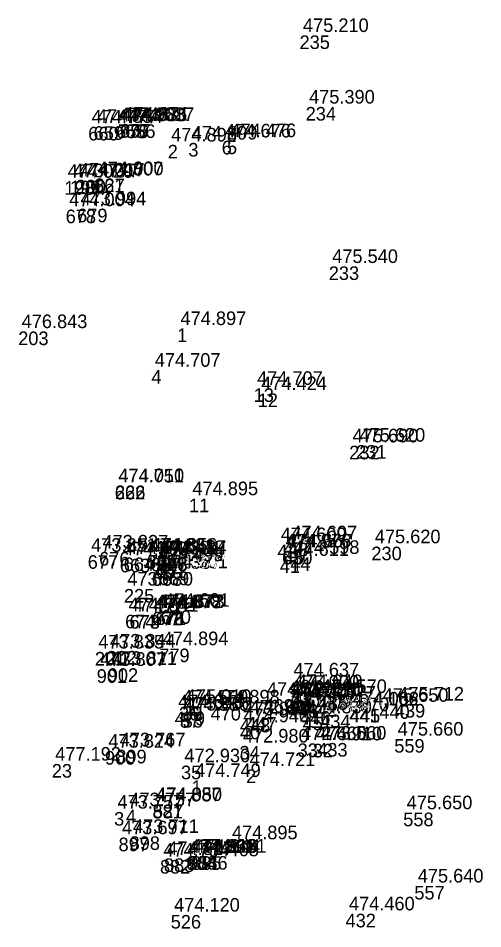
# Model space of a CAD drawing. Extents: x -874038 to -859694, y -1059487 to -1049069.
# Drawn here: x -866291.5 to -866250.5, y -1053623.2 to -1053542.8 of the extents above; entities that cross this region are included whole.
import ezdxf

# ---------------------------------------------------------------- set-up
doc = ezdxf.new("R2010")
doc.units = 0
doc.layers.add('Vrstva 60', color=7, linetype='Continuous')
doc.layers.add('Vrstva 61', color=7, linetype='Continuous')

msp = doc.modelspace()

# ---------------------------------------------------------------- linework, layer by layer
at = {"layer": 'Vrstva 60'}
for p, q in [((-866266.66, -1053544.29), (-866266.66, -1053544.29)), ((-866266.12, -1053550.61), (-866266.12, -1053550.61)), ((-866285.309, -1053552.368), (-866285.309, -1053552.368)), ((-866284.837, -1053552.312), (-866284.837, -1053552.312)), ((-866282.84, -1053552.167), (-866282.84, -1053552.167)), ((-866282.67, -1053552.158), (-866282.67, -1053552.158)), ((-866282.504, -1053552.123), (-866282.504, -1053552.123)), ((-866282.052, -1053552.148), (-866282.052, -1053552.148)), ((-866273.528, -1053553.602), (-866273.528, -1053553.602)), ((-866273.063, -1053553.574), (-866273.063, -1053553.574)), ((-866278.293, -1053553.959), (-866278.293, -1053553.959)), ((-866276.474, -1053553.789), (-866276.474, -1053553.789)), ((-866287.42, -1053557.163), (-866287.42, -1053557.163)), ((-866286.917, -1053557.123), (-866286.917, -1053557.123)), ((-866286.424, -1053557.048), (-866286.424, -1053557.048)), ((-866284.792, -1053556.958), (-866284.792, -1053556.958)), ((-866284.76, -1053556.93), (-866284.76, -1053556.93)), ((-866287.297, -1053559.672), (-866287.297, -1053559.672)), ((-866286.287, -1053559.592), (-866286.287, -1053559.592)), ((-866264.08, -1053564.69), (-866264.08, -1053564.69)), ((-866291.485, -1053570.442), (-866291.485, -1053570.442)), ((-866277.464, -1053570.168), (-866277.464, -1053570.168)), ((-866279.734, -1053573.851), (-866279.734, -1053573.851)), ((-866270.709, -1053575.454), (-866270.709, -1053575.454)), ((-866270.35, -1053575.915), (-866270.35, -1053575.915)), ((-866262.28, -1053580.53), (-866262.28, -1053580.53)), ((-866261.67, -1053580.47), (-866261.67, -1053580.47)), ((-866282.964, -1053584.073), (-866282.964, -1053584.073)), ((-866282.94, -1053584.04), (-866282.94, -1053584.04)), ((-866276.418, -1053585.197), (-866276.418, -1053585.197)), ((-866268.617, -1053589.257), (-866268.617, -1053589.257)), ((-866268.204, -1053589.812), (-866268.204, -1053589.812)), ((-866268.058, -1053589.809), (-866268.058, -1053589.809)), ((-866267.68, -1053589.093), (-866267.68, -1053589.093)), ((-866260.32, -1053589.44), (-866260.32, -1053589.44)), ((-866285.354, -1053590.193), (-866285.354, -1053590.193)), ((-866284.349, -1053589.908), (-866284.349, -1053589.908)), ((-866282.521, -1053590.507), (-866282.521, -1053590.507)), ((-866282.18, -1053590.397), (-866282.18, -1053590.397)), ((-866280.194, -1053590.203), (-866280.194, -1053590.203)), ((-866280.02, -1053590.185), (-866280.02, -1053590.185)), ((-866279.797, -1053590.432), (-866279.797, -1053590.432)), ((-866279.219, -1053590.378), (-866279.219, -1053590.378)), ((-866279.208, -1053590.399), (-866279.208, -1053590.399)), ((-866268.403, -1053590.552), (-866268.403, -1053590.552)), ((-866267.477, -1053590.382), (-866267.477, -1053590.382)), ((-866279.483, -1053591.029), (-866279.483, -1053591.029)), ((-866279.339, -1053590.998), (-866279.339, -1053590.998)), ((-866279.699, -1053591.698), (-866279.699, -1053591.698)), ((-866279.084, -1053591.643), (-866279.084, -1053591.643)), ((-866282.16, -1053593.18), (-866282.16, -1053593.18)), ((-866282.052, -1053595.45), (-866282.052, -1053595.45)), ((-866279.67, -1053595.187), (-866279.67, -1053595.187)), ((-866279.5, -1053595.169), (-866279.5, -1053595.169)), ((-866279.361, -1053595.157), (-866279.361, -1053595.157)), ((-866278.924, -1053595.053), (-866278.924, -1053595.053)), ((-866281.664, -1053595.483), (-866281.664, -1053595.483)), ((-866283.691, -1053598.653), (-866283.691, -1053598.653)), ((-866279.039, -1053598.442), (-866279.039, -1053598.442)), ((-866284.721, -1053598.737), (-866284.721, -1053598.737)), ((-866284.559, -1053600.268), (-866284.559, -1053600.268)), ((-866283.584, -1053600.183), (-866283.584, -1053600.183)), ((-866267.5, -1053601.203), (-866267.5, -1053601.203)), ((-866267.51, -1053602.29), (-866267.51, -1053602.29)), ((-866267.21, -1053602.23), (-866267.21, -1053602.23)), ((-866265.06, -1053602.66), (-866265.06, -1053602.66)), ((-866269.841, -1053602.908), (-866269.841, -1053602.908)), ((-866267.787, -1053603.047), (-866267.787, -1053603.047)), ((-866267.685, -1053603.337), (-866267.685, -1053603.337)), ((-866267.4, -1053602.93), (-866267.4, -1053602.93)), ((-866267.13, -1053602.95), (-866267.13, -1053602.95)), ((-866266.018, -1053603.251), (-866266.018, -1053603.251)), ((-866259.62, -1053603.44), (-866259.62, -1053603.44)), ((-866258.251, -1053603.333), (-866258.251, -1053603.333)), ((-866277.677, -1053604), (-866277.677, -1053604)), ((-866277.3, -1053603.59), (-866277.3, -1053603.59)), ((-866277.23, -1053604.23), (-866277.23, -1053604.23)), ((-866277.01, -1053603.54), (-866277.01, -1053603.54)), ((-866276.97, -1053604.21), (-866276.97, -1053604.21)), ((-866274.513, -1053603.588), (-866274.513, -1053603.588)), ((-866266.619, -1053603.96), (-866266.619, -1053603.96)), ((-866264.84, -1053604.27), (-866264.84, -1053604.27)), ((-866262.268, -1053603.752), (-866262.268, -1053603.752)), ((-866262.218, -1053603.768), (-866262.218, -1053603.768)), ((-866271.915, -1053604.639), (-866271.915, -1053604.639)), ((-866271.355, -1053604.476), (-866271.355, -1053604.476)), ((-866266.38, -1053604.46), (-866266.38, -1053604.46)), ((-866271.92, -1053605.25), (-866271.92, -1053605.25)), ((-866258.3, -1053606.43), (-866258.3, -1053606.43)), ((-866283.827, -1053607.492), (-866283.827, -1053607.492)), ((-866282.832, -1053607.378), (-866282.832, -1053607.378)), ((-866271.96, -1053607.04), (-866271.96, -1053607.04)), ((-866266.83, -1053606.82), (-866266.83, -1053606.82)), ((-866265.49, -1053606.85), (-866265.49, -1053606.85)), ((-866265.1, -1053606.78), (-866265.1, -1053606.78)), ((-866288.522, -1053608.638), (-866288.522, -1053608.638)), ((-866277.12, -1053608.78), (-866277.12, -1053608.78)), ((-866271.368, -1053609.114), (-866271.368, -1053609.114)), ((-866276.185, -1053610.084), (-866276.185, -1053610.084)), ((-866279.642, -1053612.238), (-866279.642, -1053612.238)), ((-866279.6, -1053612.2), (-866279.6, -1053612.2)), ((-866283.026, -1053612.874), (-866283.026, -1053612.874)), ((-866281.981, -1053612.667), (-866281.981, -1053612.667)), ((-866257.51, -1053612.93), (-866257.51, -1053612.93)), ((-866282.632, -1053615.138), (-866282.632, -1053615.138)), ((-866281.654, -1053615.023), (-866281.654, -1053615.023)), ((-866272.931, -1053615.579), (-866272.931, -1053615.579)), ((-866278.977, -1053617.112), (-866278.977, -1053617.112)), ((-866278.629, -1053616.968), (-866278.629, -1053616.968)), ((-866276.634, -1053616.793), (-866276.634, -1053616.793)), ((-866276.461, -1053616.766), (-866276.461, -1053616.766)), ((-866276.227, -1053616.782), (-866276.227, -1053616.782)), ((-866275.684, -1053616.763), (-866275.684, -1053616.763)), ((-866256.53, -1053619.4), (-866256.53, -1053619.4)), ((-866278.03, -1053621.97), (-866278.03, -1053621.97)), ((-866262.6, -1053621.86), (-866262.6, -1053621.86))]:
    msp.add_line(p, q, dxfattribs=at)

# ---------------------------------------------------------------- texts
for s, p in [('235', (-866266.66, -1053545.49)), ('234', (-866266.12, -1053551.81)), ('660', (-866285.309, -1053553.568)), ('659', (-866284.837, -1053553.512)), ('658', (-866282.84, -1053553.367)), ('776', (-866282.67, -1053553.358)), ('657', (-866282.504, -1053553.323)), ('656', (-866282.052, -1053553.348)), ('6', (-866273.528, -1053554.802)), ('5', (-866273.063, -1053554.774)), ('2', (-866278.293, -1053555.159)), ('3', (-866276.474, -1053554.989)), ('198', (-866287.42, -1053558.363)), ('199', (-866286.917, -1053558.323)), ('200', (-866286.424, -1053558.248)), ('661', (-866284.792, -1053558.158)), ('227', (-866284.76, -1053558.13)), ('678', (-866287.297, -1053560.872)), ('679', (-866286.287, -1053560.792)), ('233', (-866264.08, -1053565.89)), ('203', (-866291.485, -1053571.642)), ('1', (-866277.464, -1053571.368)), ('4', (-866279.734, -1053575.051)), ('13', (-866270.709, -1053576.654)), ('12', (-866270.35, -1053577.115)), ('232', (-866262.28, -1053581.73)), ('231', (-866261.67, -1053581.67)), ('662', (-866282.964, -1053585.273)), ('226', (-866282.94, -1053585.24)), ('11', (-866276.418, -1053586.397)), ('42', (-866268.617, -1053590.457)), ('630', (-866268.204, -1053591.012)), ('45', (-866268.058, -1053591.009)), ('43', (-866267.68, -1053590.293)), ('230', (-866260.32, -1053590.64)), ('677', (-866285.354, -1053591.393)), ('676', (-866284.349, -1053591.108)), ('663', (-866282.521, -1053591.707)), ('664', (-866282.18, -1053591.597)), ('665', (-866280.194, -1053591.403)), ('777', (-866280.02, -1053591.385)), ('667', (-866279.797, -1053591.632)), ('666', (-866279.219, -1053591.578)), ('928', (-866279.208, -1053591.599)), ('41', (-866268.403, -1053591.752)), ('44', (-866267.477, -1053591.582)), ('40', (-866279.483, -1053592.229)), ('651', (-866279.339, -1053592.198)), ('668', (-866279.699, -1053592.898)), ('669', (-866279.084, -1053592.843)), ('225', (-866282.16, -1053594.38)), ('674', (-866282.052, -1053596.65)), ('672', (-866279.67, -1053596.387)), ('778', (-866279.5, -1053596.369)), ('671', (-866279.361, -1053596.357)), ('670', (-866278.924, -1053596.253)), ('673', (-866281.664, -1053596.683)), ('202', (-866283.691, -1053599.853)), ('779', (-866279.039, -1053599.642)), ('201', (-866284.721, -1053599.937)), ('901', (-866284.559, -1053601.468)), ('902', (-866283.584, -1053601.383)), ('481', (-866267.5, -1053602.403)), ('43', (-866267.51, -1053603.49)), ('42', (-866267.21, -1053603.43)), ('435', (-866265.06, -1053603.86)), ('469', (-866269.841, -1053604.108)), ('444', (-866267.787, -1053604.247)), ('443', (-866267.685, -1053604.537)), ('44', (-866267.4, -1053604.13)), ('41', (-866267.13, -1053604.15)), ('442', (-866266.018, -1053604.451)), ('440', (-866259.62, -1053604.64)), ('439', (-866258.251, -1053604.533)), ('479', (-866277.677, -1053605.2)), ('36', (-866277.3, -1053604.79)), ('37', (-866277.23, -1053605.43)), ('39', (-866277.01, -1053604.74)), ('38', (-866276.97, -1053605.41)), ('470', (-866274.513, -1053604.788)), ('446', (-866266.619, -1053605.16)), ('434', (-866264.84, -1053605.47)), ('441', (-866262.268, -1053604.952)), ('445', (-866262.218, -1053604.968)), ('448', (-866271.915, -1053605.839)), ('447', (-866271.355, -1053605.676)), ('45', (-866266.38, -1053605.66)), ('40', (-866271.92, -1053606.45)), ('559', (-866258.3, -1053607.63)), ('900', (-866283.827, -1053608.692)), ('899', (-866282.832, -1053608.578)), ('34', (-866271.96, -1053608.24)), ('33', (-866266.83, -1053608.02)), ('32', (-866265.49, -1053608.05)), ('433', (-866265.1, -1053607.98)), ('23', (-866288.522, -1053609.838)), ('35', (-866277.12, -1053609.98)), ('2', (-866271.368, -1053610.314)), ('1', (-866276.185, -1053611.284)), ('881', (-866279.642, -1053613.438)), ('527', (-866279.6, -1053613.4)), ('3', (-866283.026, -1053614.074)), ('4', (-866281.981, -1053613.867)), ('558', (-866257.51, -1053614.13)), ('897', (-866282.632, -1053616.338)), ('898', (-866281.654, -1053616.223)), ('468', (-866272.931, -1053616.779)), ('882', (-866278.977, -1053618.312)), ('883', (-866278.629, -1053618.168)), ('884', (-866276.634, -1053617.993)), ('951', (-866276.461, -1053617.966)), ('885', (-866276.227, -1053617.982)), ('886', (-866275.684, -1053617.963)), ('557', (-866256.53, -1053620.6)), ('526', (-866278.03, -1053623.17)), ('432', (-866262.6, -1053623.06))]:
    msp.add_text(s, height=1.2, dxfattribs=at).set_placement(p)
at = {"layer": 'Vrstva 61'}
for s, p in [('475.210', (-866266.36, -1053543.99)), ('475.390', (-866265.82, -1053550.31)), ('474.777', (-866285.009, -1053552.068)), ('474.854', (-866284.537, -1053552.012)), ('474.908', (-866282.54, -1053551.867)), ('474.885', (-866282.37, -1053551.858)), ('474.871', (-866282.204, -1053551.823)), ('474.617', (-866281.752, -1053551.848)), ('474.898', (-866277.993, -1053553.659)), ('474.899', (-866276.174, -1053553.489)), ('474.676', (-866273.228, -1053553.302)), ('474.476', (-866272.763, -1053553.274)), ('474.029', (-866287.12, -1053556.863)), ('473.777', (-866286.617, -1053556.823)), ('474.017', (-866286.124, -1053556.748)), ('474.807', (-866284.492, -1053556.658)), ('474.000', (-866284.46, -1053556.63)), ('474.004', (-866286.997, -1053559.372)), ('473.994', (-866285.987, -1053559.292)), ('475.540', (-866263.78, -1053564.39)), ('474.897', (-866277.164, -1053569.868)), ('476.843', (-866291.185, -1053570.142)), ('474.707', (-866279.434, -1053573.551)), ('474.707', (-866270.409, -1053575.154)), ('474.424', (-866270.05, -1053575.615)), ('475.690', (-866261.98, -1053580.23)), ('475.620', (-866261.37, -1053580.17)), ('474.751', (-866282.664, -1053583.773)), ('474.010', (-866282.64, -1053583.74)), ('474.895', (-866276.118, -1053584.897)), ('474.609', (-866268.317, -1053588.957)), ('474.607', (-866267.38, -1053588.793)), ('475.620', (-866260.02, -1053589.14)), ('473.851', (-866285.054, -1053589.893)), ('473.827', (-866284.049, -1053589.608)), ('474.793', (-866282.221, -1053590.207)), ('474.848', (-866281.88, -1053590.097)), ('474.881', (-866279.894, -1053589.903)), ('474.856', (-866279.72, -1053589.885)), ('474.384', (-866279.497, -1053590.132)), ('474.437', (-866278.919, -1053590.078)), ('474.414', (-866278.908, -1053590.099)), ('474.976', (-866267.904, -1053589.512)), ('474.667', (-866267.758, -1053589.509)), ('474.598', (-866267.177, -1053590.082)), ('474.499', (-866279.183, -1053590.729)), ('474.975', (-866279.039, -1053590.698)), ('474.611', (-866268.103, -1053590.252)), ('474.387', (-866279.399, -1053591.398)), ('474.501', (-866278.784, -1053591.343)), ('473.970', (-866281.86, -1053592.88)), ('474.878', (-866279.37, -1053594.887)), ('474.872', (-866279.2, -1053594.869)), ('474.873', (-866279.061, -1053594.857)), ('474.601', (-866278.624, -1053594.753)), ('474.772', (-866281.752, -1053595.15)), ('474.841', (-866281.364, -1053595.183)), ('474.894', (-866278.739, -1053598.142)), ('473.835', (-866284.421, -1053598.437)), ('473.844', (-866283.391, -1053598.353)), ('473.811', (-866283.284, -1053599.883)), ('473.807', (-866284.259, -1053599.968)), ('474.637', (-866267.2, -1053600.903)), ('475.000', (-866267.21, -1053601.99)), ('474.640', (-866266.91, -1053601.93)), ('474.897', (-866269.541, -1053602.608)), ('474.729', (-866267.487, -1053602.747)), ('474.497', (-866267.385, -1053603.037)), ('475.010', (-866267.1, -1053602.63)), ('474.570', (-866266.83, -1053602.65)), ('473.977', (-866265.718, -1053602.951)), ('474.570', (-866264.76, -1053602.36)), ('475.712', (-866257.951, -1053603.033)), ('474.648', (-866277.377, -1053603.7)), ('474.550', (-866277, -1053603.29)), ('475.010', (-866276.71, -1053603.24)), ('475.000', (-866276.67, -1053603.91)), ('474.898', (-866274.213, -1053603.288)), ('471.292', (-866266.319, -1053603.66)), ('474.106', (-866261.968, -1053603.452)), ('474.062', (-866261.918, -1053603.468)), ('475.650', (-866259.32, -1053603.14)), ('474.580', (-866276.93, -1053603.93)), ('473.993', (-866271.615, -1053604.339)), ('472.681', (-866271.055, -1053604.176)), ('474.830', (-866266.08, -1053604.16)), ('474.570', (-866264.54, -1053603.97)), ('474.940', (-866271.62, -1053604.95)), ('475.660', (-866258, -1053606.13)), ('473.767', (-866282.532, -1053607.078)), ('472.980', (-866271.66, -1053606.74)), ('472.660', (-866266.53, -1053606.52)), ('474.910', (-866265.19, -1053606.55)), ('473.560', (-866264.8, -1053606.48)), ('473.824', (-866283.527, -1053607.192)), ('477.192', (-866288.222, -1053608.338)), ('472.930', (-866276.82, -1053608.48)), ('474.721', (-866271.068, -1053608.814)), ('474.749', (-866275.885, -1053609.784)), ('474.887', (-866279.342, -1053611.938)), ('474.050', (-866279.3, -1053611.9)), ('473.757', (-866282.726, -1053612.574)), ('473.757', (-866281.681, -1053612.367)), ('475.650', (-866257.21, -1053612.63)), ('473.697', (-866282.332, -1053614.838)), ('473.711', (-866281.354, -1053614.723)), ('474.895', (-866272.631, -1053615.279)), ('474.827', (-866278.329, -1053616.668)), ('474.891', (-866276.334, -1053616.493)), ('474.916', (-866276.161, -1053616.466)), ('474.944', (-866275.927, -1053616.482)), ('474.681', (-866275.384, -1053616.463)), ('474.754', (-866278.677, -1053616.812)), ('475.640', (-866256.23, -1053619.1)), ('474.460', (-866262.3, -1053621.56)), ('474.120', (-866277.73, -1053621.67))]:
    msp.add_text(s, height=1.2, dxfattribs=at).set_placement(p)

doc.saveas('drawing.dxf')
